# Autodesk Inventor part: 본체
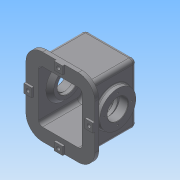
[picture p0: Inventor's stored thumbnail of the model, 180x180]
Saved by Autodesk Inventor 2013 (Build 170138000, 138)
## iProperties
Created: 2014-11
Part Number: 본체
Material: Generic
Document SubType Name: Modeling
Designer: Administrator
Density: 1 g/cm^3
Author: Administrator
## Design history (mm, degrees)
sketch "Sketch1"
  geometry: L1 (-65, 64)-(65, 64); L2 (65, 64)-(65, -64); L3 (65, -64)-(-65, -64); L4 (-65, -64)-(-65, 64); L5 (-65, 64)-(65, -64); L6 (65, 64)-(-65, -64); 1 further point
  constraints: 12 end point, 2 midpoint, 2 parallel, 1 horizontal, 1 perpendicular
  dimensions: "d0" = 130 distance of L2.end L3.end; "d2" = 128 distance of L1.end L2.end
extrude "Extrusion1" new body sketch "Sketch1" stored distance "d3" = 152; taper "d4" = 0 deg
sketch "Sketch3"
  geometry: L1 (-22, -174)-(152, -174); L2 (152, -174)-(152, 22); L3 (152, 22)-(-22, 22); L4 (-22, 22)-(-22, -174); L5 (-22, -174)-(152, 22); L6 (152, -174)-(-22, 22); 1 further point
  constraints: 12 end point, 2 midpoint, 2 parallel, 1 horizontal, 1 perpendicular
  dimensions: "d8" = 196 distance of L1.end L2.end; "d10" = 174 distance of L2.end L3.end
extrude "Extrusion2" join sketch "Sketch3" distance "d11" = 10; taper "d12" = 0 deg
sketch "Sketch4"
  geometry: L1 (0, 0)-(174, 0) reference; L2 (174, 0)-(174, 196) reference; L3 (174, 196)-(0, 196) reference; L4 (0, 196)-(0, 0) reference; L5 (76, 196)-(98, 196); L6 (98, 196)-(98, 176); L7 (98, 176)-(76, 176); L8 (76, 176)-(76, 196); L9 (154, 109)-(174, 109); L10 (174, 109)-(174, 87); L11 (174, 87)-(154, 87); L12 (154, 87)-(154, 109); L13 (76, 20)-(98, 20); L14 (98, 20)-(98, 0); L15 (98, 0)-(76, 0); L16 (76, 0)-(76, 20); L17 (0, 109)-(20, 109); L18 (20, 109)-(20, 87); L19 (20, 87)-(0, 87); L20 (0, 87)-(0, 109); 5 further points
  constraints: 32 end point, 8 parallel, 7 midpoint, 4 horizontal, 4 perpendicular, 1 collinear, 1 vertical alignment
  dimensions: "d13" = 22 distance of L6.end L7.end; "d16" = 20 distance of L5.end L6.end; "d17" = 22 distance of L11.end L9.start; "d18" = 20 distance of L10.end L11.end; "d19" = 22 distance of L13.start L13.end; "d20" = 20 distance of L13.end L14.end; "d21" = 22 distance of L17.end L18.end; "d22" = 20 distance of L17.start L17.end
extrude "Extrusion3" join sketch "Sketch4" distance "d23" = 5; taper "d24" = 0 deg
sketch "Sketch11"
  geometry: L1 (-22, -118)-(0, -118) reference; L2 (0, -118)-(152, -118) reference; L3 (152, -118)-(174, -118) reference; L4 (174, -118)-(174, -128) reference; L5 (174, -128)-(-22, -128) reference; L6 (-22, -128)-(-22, -118) reference; L7 (0, -118)-(0, 0) reference; L8 (0, 0)-(152, 0) reference; L9 (152, 0)-(152, -118) reference; L10 (76, -118)-(76, -60); C1 r 45.5 at (76, -60); 1 further point
  constraints: 2 end point, 1 centre point, 1 coincident, 1 midpoint, 1 parallel
  dimensions: "d40" = 58 distance of L10.start L10.end; "d41" = 91 diameter of C1
extrude "Extrusion5" join sketch "Sketch11" distance "d42" = 12; taper "d43" = 0 deg
mirror "Mirror1"
sketch "Sketch14"
  geometry: L1 (0, 0)-(84.121, -17.88); L2 (84.121, -17.88)-(90.566, 12.442); L3 (90.566, 12.442)-(64, 18.089); L4 (84.121, -17.88)-(77.675, -48.203); L5 (77.675, -48.203)-(64, -45.296); L6 (64, 76)-(-54, 76) reference; L7 (-54, -76)-(-54, -98) reference; L8 (-54, -98)-(-69, -98) reference; L9 (-69, -98)-(-69, -78) reference; L10 (-69, -78)-(-64, -78) reference; L11 (-64, -78)-(-64, 78) reference; L12 (-64, 78)-(-69, 78) reference; L13 (-69, 78)-(-69, 98) reference; L14 (-69, 98)-(-54, 98) reference; L15 (-54, 98)-(-54, 76) reference; L16 (-54, 76)-(64, 76) reference; L17 (64, 76)-(64, -76) reference; L18 (64, -76)-(-54, -76) reference
  constraints: 10 end point, 3 perpendicular, 2 point on line, 1 parallel
  dimensions: "d46" = 168 deg angle of L6 L1; "d47" = 31 distance between parallel lines of L3 L1; "d49" = 31 distance between parallel lines of L5 L1; "d50" = 86 distance from line of L1.start L4
extrude "Extrusion6" join sketch "Sketch14" stored distance "d51" = 62; taper "d52" = 0 deg
fillet "Fillet1" dims "d53" = 31
sketch "Sketch16"
  geometry: L1 (-54, -76)-(-54, -98) reference; L2 (-54, -98)-(-69, -98) reference; L3 (-69, -98)-(-69, -78) reference; L4 (-69, -78)-(-64, -78) reference; L5 (-64, -78)-(-64, 78) reference; L6 (-64, 78)-(-69, 78) reference; L7 (-69, 78)-(-69, 98) reference; L8 (-69, 98)-(-54, 98) reference; L9 (-54, 98)-(-54, 76) reference; L10 (-54, 76)-(64, 76) reference; L11 (64, 76)-(64, 18.089) reference; L12 (64, 18.089)-(90.566, 12.442) reference; L13 (90.566, 12.442)-(77.675, -48.203) reference; L14 (77.675, -48.203)-(64, -45.296) reference; L15 (64, -45.296)-(64, -76) reference; L16 (64, -76)-(-54, -76) reference; L17 (-54, -76)-(-54, -98) reference; L18 (-54, -98)-(-69, -98) reference; L19 (-69, -98)-(-69, -78) reference; L20 (-69, -78)-(-64, -78) reference; L21 (-64, -78)-(-64, 78) reference; L22 (-64, 78)-(-69, 78) reference; L23 (-69, 78)-(-69, 98) reference; L24 (-69, 98)-(-54, 98) reference; L25 (-54, 98)-(-54, 76) reference; L26 (-54, 76)-(64, 76) reference; L27 (64, 76)-(64, 18.089) reference; L28 (64, 18.089)-(90.566, 12.442) reference; L29 (90.566, 12.442)-(77.675, -48.203) reference; L30 (77.675, -48.203)-(64, -45.296) reference; L31 (64, -45.296)-(64, -76) reference; L32 (64, -76)-(-54, -76) reference; L33 (54, 46)-(54, -46); L34 (34, 66)-(-64, 66); L35 (34, -66)-(-64, -66); A1 r 20 centre (34, 46) between (54, 46) and (34, 66); A2 r 20 centre (34, -46) between (34, -66) and (54, -46); 1 further point
  constraints: 6 end point, 4 point on circle, 4 tangent, 2 centre point, 2 perpendicular, 2 point on line, 1 equal radius
  dimensions: "d55" = 20 radius of A1; "d56" = 10 distance between parallel lines of L34 L10; "d57" = 10 distance between parallel lines of L16 L35; "d58" = 10 distance between parallel lines of L11 L33
extrude "Extrusion7" cut sketch "Sketch16" stored distance "d59" = 110; taper "d60" = 0 deg
sketch "Sketch17"
  geometry: C1 r 45.5 at (0, 0) reference; C2 r 26 at (0, 0); 1 further point
  constraints: 1 centre point, 1 coincident
  dimensions: "d61" = 52 diameter of C2
extrude "Extrusion8" cut sketch "Sketch17" distance "d62" = 32; taper "d63" = 0 deg
sketch "Sketch18"
  geometry: C1 r 45.5 at (0, 0) reference; C2 r 26 at (0, 0); 1 further point
  constraints: 1 centre point, 1 coincident
  dimensions: "d64" = 52 diameter of C2
extrude "Extrusion9" cut sketch "Sketch18" distance "d65" = 32; taper "d66" = 0 deg
sketch "Sketch19"
  geometry: C1 r 26 at (0, 0) reference; 2 further points
  constraints: 1 vertical alignment
  dimensions: "d67" = 35 distance of point (0, 35) C1.centre
hole "Hole1" sketch "Sketch19" at (0, 35) diameter "d68" = 3.242; stored, may be unused: countersink angle "d72" = 90 deg, drill point angle "d74" = 118 deg; dims "d69" = 13, "d70" = 4, "d71" = 2, "d73" = 16
pattern_circular "Circular Pattern1" dims angle "d76" = 360 deg
mirror "Mirror2"
hole "Hole2" sketch "Sketch20" diameter "d79" = 9; stored, may be unused: countersink angle "d83" = 90 deg, drill point angle "d85" = 0 deg; dims "d80" = 13, "d81" = 14, "d82" = 8.6, "d84" = 15
mirror "Mirror3"
sketch "Sketch21"
  geometry: L1 (-22, -22)-(152, -22) reference; 2 further points
  constraints: 1 vertical alignment
  dimensions: "d89" = 10 distance from line of L1 point (65, -12)
hole "Hole3" sketch "Sketch21" at (65, -12) diameter "d90" = 9; stored, may be unused: countersink angle "d94" = 90 deg, drill point angle "d96" = 0 deg; dims "d91" = 13, "d92" = 14, "d93" = 8.6, "d95" = 15
mirror "Mirror4"
fillet "Fillet2" dims "d97" = 10
sketch "Sketch23"
  geometry: L1 (-84, -62.6)-(-81.5, -62.6) reference; L2 (-81.5, -62.6)-(-81.5, -69) reference; L3 (-81.5, -69)-(-87, -69) reference; L4 (-87, -69)-(-87, -54) reference; L5 (-87, -54)-(-84, -54) reference; L6 (-84, -54)-(-84, -62.6) reference; L7 (81.5, -62.6)-(84, -62.6) reference; L8 (84, -62.6)-(84, -54) reference; L9 (84, -54)-(87, -54) reference; L10 (87, -54)-(87, -69) reference; L11 (87, -69)-(81.5, -69) reference; L12 (81.5, -69)-(81.5, -62.6) reference; L13 (-55, 30)-(-77, 30) reference; L14 (-77, 30)-(-77, 37.379) reference; L15 (-77, 37.379)-(-61, 37.379) reference; L16 (-55, 54)-(-55, 30) reference; L17 (-77, -22)-(-55, -22) reference; L18 (-55, -22)-(-55, -64) reference; L19 (-61, -29.379)-(-77, -29.379) reference; L20 (-77, -29.379)-(-77, -22) reference; L21 (77, 30)-(55, 30) reference; L22 (55, 30)-(55, 54) reference; L23 (61, 37.379)-(77, 37.379) reference; L24 (77, 37.379)-(77, 30) reference; L25 (55, -22)-(77, -22) reference; L26 (77, -22)-(77, -29.379) reference; L27 (77, -29.379)-(61, -29.379) reference; L28 (55, -64)-(55, -22) reference; L29 (65, 49.5)-(77, 49.5) reference; L30 (77, 49.5)-(77, 40.621) reference; L31 (77, 40.621)-(61, 40.621) reference; L32 (55, 54)-(-55, 54) reference; L33 (-61, 40.621)-(-77, 40.621) reference; L34 (-77, 40.621)-(-77, 49.5) reference; L35 (-77, 49.5)-(-65, 49.5) reference; L36 (-55, 64)-(-27.999, 64) reference; L37 (-25.037, 87.921)-(25.037, 87.921) reference; L38 (27.999, 64)-(55, 64) reference; L39 (-67, -64)-(-67, -69) reference; L40 (-67, -69)-(-72.5, -69) reference; L41 (-72.5, -69)-(-72.5, -62.6) reference; L42 (-72.5, -62.6)-(-70, -62.6) reference; L43 (-70, -62.6)-(-70, -54) reference; L44 (-70, -54)-(-65, -54) reference; L45 (-65, -54)-(-65, -41.5) reference; L46 (-65, -41.5)-(-77, -41.5) reference; L47 (-77, -41.5)-(-77, -32.621) reference; L48 (-77, -32.621)-(-61, -32.621) reference; L49 (-55, -64)-(-67, -64) reference; L50 (67, -69)-(67, -64) reference; L51 (67, -64)-(55, -64) reference; L52 (61, -32.621)-(77, -32.621) reference; L53 (77, -32.621)-(77, -41.5) reference; L54 (77, -41.5)-(65, -41.5) reference; L55 (65, -41.5)-(65, -54) reference; L56 (65, -54)-(70, -54) reference; L57 (70, -54)-(70, -62.6) reference; L58 (70, -62.6)-(72.5, -62.6) reference; L59 (72.5, -62.6)-(72.5, -69) reference; L60 (72.5, -69)-(67, -69) reference; L61 (-55, 45.5)-(-45, 35.5); L62 (-45, 35.5)-(-45, 26); L63 (-45, 26)-(-55, 26); L64 (-55, 26)-(-55, 45.5)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; A1 r 10 centre (-55, 54) between (-55, 64) and (-65, 54) reference; A2 r 10 centre (55, 54) between (65, 54) and (55, 64) reference; 2 further points; 2 other entities
  constraints: 10 end point, 4 perpendicular, 1 point on line, 2 other
  dimensions: "d99" = 52 diameter of L63 L65; "d101" = 71 diameter of L61.end L65; "d102" = 91 diameter of L61.start L65; "d103" = 10 distance between parallel lines of L62 L16
revolve "Revolution1" sketch "Sketch23" stored, may be unused: angle "d104" = 90 deg
mirror "Mirror5"
hole "Hole4" diameter "d107" = 30; stored, may be unused: countersink angle "d111" = 90 deg, drill point angle "d113" = 0 deg; dims "d105" = 10, "d106" = 10, "d108" = 13, "d109" = 42, "d110" = 25, "d112" = 15
sketch "Sketch24"
  geometry: L1 (-55, 54)-(-55, -54) reference; L2 (-87, -54)-(-55, -54) reference; L3 (-87, -64)-(-87, -54) reference; L4 (87, -64)-(-87, -64) reference; L5 (87, -54)-(87, -64) reference; L6 (55, -54)-(87, -54) reference; L7 (-55, -54)-(55, -54) reference; L8 (55, 54)-(-55, 54) reference; L9 (55, -54)-(55, 54) reference; L10 (-55, 54)-(-55, -54) reference; L11 (-87, -54)-(-55, -54) reference; L12 (-87, -64)-(-87, -54) reference; L13 (87, -64)-(-87, -64) reference; L14 (87, -54)-(87, -64) reference; L15 (55, -54)-(87, -54) reference; L16 (-55, -54)-(55, -54) reference; L17 (55, 54)-(-55, 54) reference; L18 (55, -54)-(55, 54) reference; 2 further points
  constraints: 1 vertical alignment, 1 other
  dimensions: "d114" = 92 distance from line of L4 point (0, 28)
emboss "Emboss1" sketch "Sketch24" dims "d0" = 130, "d2" = 128, "d115" = 1, "d116" = 0
fillet "Fillet3" dims "d117" = 10
fillet "Fillet4" dims "d118" = 3
chamfer "Chamfer1" distance "d120" = 1; stored, may be unused: second distance "d121" = 2, angle "d122" = 45 deg
fillet "Fillet6" dims "d123" = 42
fillet "Fillet7" dims "d124" = 3
fillet "Fillet8" dims "d125" = 0.3
body "Solid1"
node "Project Cut Edges5"
node "Project Cut Edges8"
node "Project Cut Edges9"
node "Project Cut Edges10"
node "Project Cut Edges14"
node "Project Cut Edges15"
node "Project Cut Edges16"
other parameters: "d88" = 10
